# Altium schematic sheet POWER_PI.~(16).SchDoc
size A; SheetNumber: 1; SheetTotal: 2
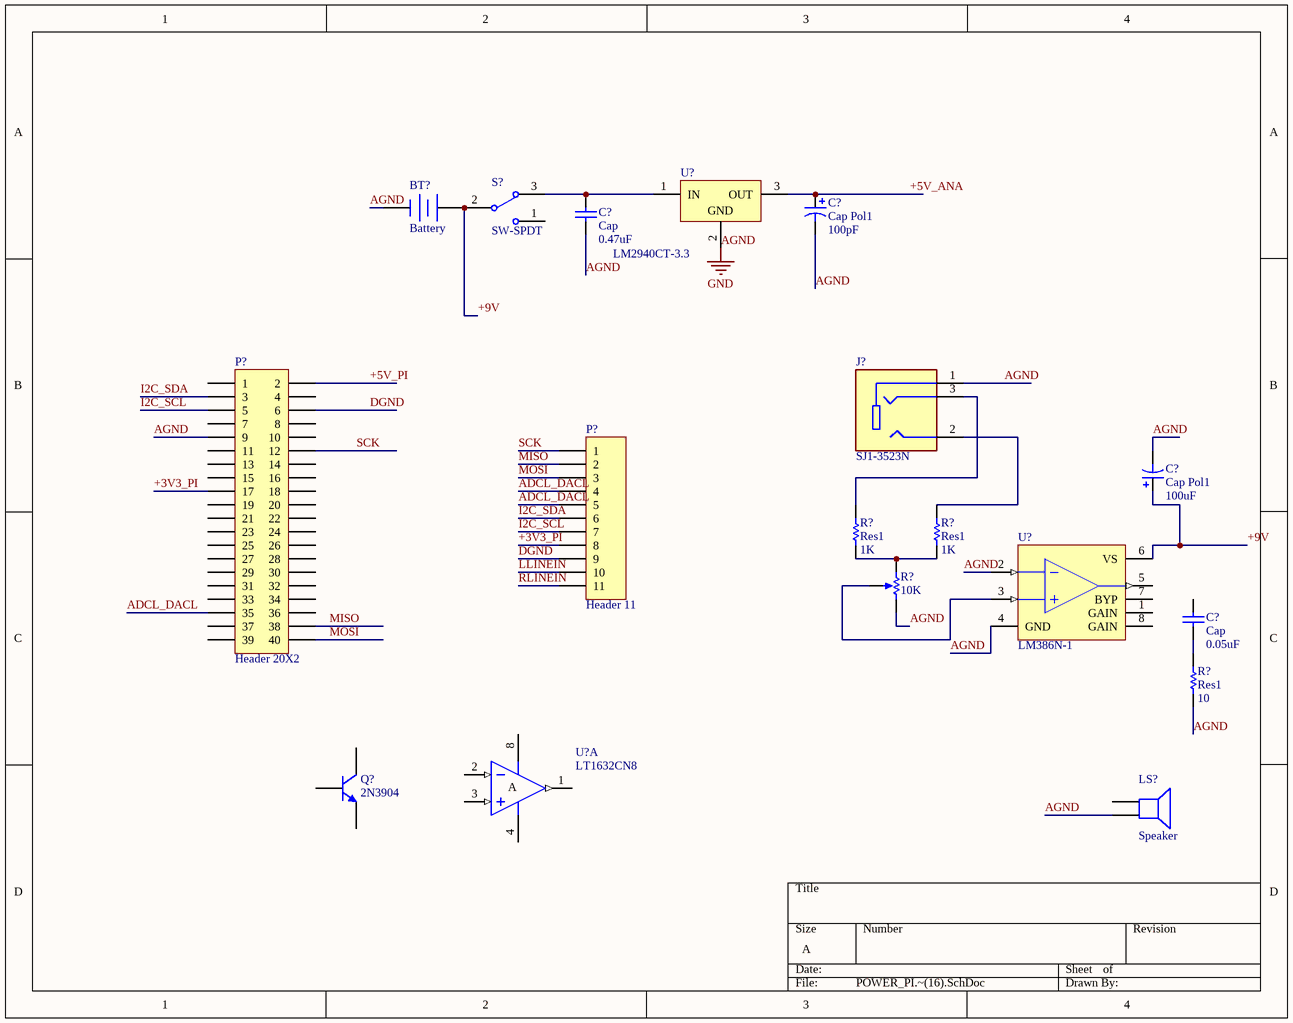
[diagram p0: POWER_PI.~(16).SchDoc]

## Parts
(Parts that share a designator on the sheet are numbered #1, #2 ... from top to bottom, then left to right.)
BT?  Battery  [BAT-2]
C?#1  Cap Pol1  value 100pF  [RB7.6-15]
C?#2  Cap  value 0.47uF  [RAD-0.3]
C?#3  Cap Pol1  value 100uF  [RB7.6-15]
C?#4  Cap  value 0.05uF  [RAD-0.3]
J?  SJ1-3523N  [CUI_SJ1-3523N]
LS?  Speaker  [PIN2]
P?#1  Header 20X2  [HDR2X20]
P?#2  Header 11  [HDR1X11]
Q?  2N3904  [TO92C]
R?#1  Res1  value 1K  [AXIAL-0.3]
R?#2  Res1  value 1K  [AXIAL-0.3]
R?#3  value 10K  [POT OFFSET 200]  (hidden comment: RPot_3)
R?#4  Res1  value 10  [AXIAL-0.3]
S?  SW-SPDT  [SW DPST jameco]
U?#1  LM2940CT-3.3  [T03B]
U?#2  LM386N-1  [DIP-8]
U?#3  LT1632CN8  [SO08]  (part A of 2)

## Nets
AGND: BT?.2(-) C?#1.2 C?#2.1 C?#3.2 J?.1 LS?.2 P?#1.9 R?#3.3(BOT) R?#4.1 U?#1.2(GND) U?#2.2(IN-) U?#2.4(GND)  [also labelled GND]
+3V3_PI: P?#1.17 P?#2.8
+5V_ANA: C?#1.1 U?#1.3(OUT)
+5V_PI: P?#1.2
+9V: BT?.1(+) C?#3.1 S?.2 U?#2.6(VS)
ADCL_DACL: P?#1.35 P?#2.4 P?#2.5
DGND: P?#1.6 P?#2.9
I2C_SCL: P?#1.5 P?#2.7
I2C_SDA: P?#1.3 P?#2.6
LLINEIN: P?#2.10
MISO: P?#1.38 P?#2.2
MOSI: P?#1.40 P?#2.3
RLINEIN: P?#2.11
SCK: P?#1.12 P?#2.1
NetC?#2_2: C?#2.2 S?.3 U?#1.1(IN)
NetC?#4_1: C?#4.1 R?#4.2
NetJ?_2: J?.2 R?#2.2
NetJ?_3: J?.3 R?#1.2
NetR?#1_1: R?#1.1 R?#2.1 R?#3.1(TOP)
NetR?#3_2: R?#3.2(TAP) U?#2.3(IN+)

Not connected (* = marked no-connect by the designer): C?#4 2; LS? 1; P?#1 1 4 7 8 10 11 13 14 15 16 18 19 20 21 22 23 24 25 26 27 28 29 30 31 32 33 34 36 37 39; Q? 1(E) 2(B) 3(C); S? 1; U?#2 1(GAIN) 5(OUT) 7(BYP) 8(GAIN); U?#3 1(OUT) 2(IN-) 3(IN+) 4(V-) 8(V+)

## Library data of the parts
BT? = Battery: Multicell Battery
C?#1 C?#3 = Cap Pol1: Polarized Capacitor (Radial)
C?#2 C?#4 = Cap: Capacitor
J? = SJ1-3523N: 3.5 mm, Stereo, Right Angle, Through Hole, 3 Conductors, 0 Internal Switches, Audio Jack Connector; MF: Same Sky
LS? = Speaker: Loudspeaker
P?#1 = Header 20X2: Header, 20-Pin, Dual row
P?#2 = Header 11: Header, 11-Pin
Q? = 2N3904: NPN General Purpose Amplifier
R?#1 R?#2 R?#4 = Res1: Resistor
R?#3 = RPot: Potentiometer; Sim Note: Enter the Resistance value and the set point into parameter fields.; Set Position: 0.5
S? = SW-SPDT: SPDT Subminiature Toggle Switch, Right Angle Mounting, Vertical Actuation
U?#1 = LM2940CT-5.0: 1A Low Dropout Regulator, 3-pin TO-220; Manufacturer: National Semiconductor; PackageTopMarking: NSUZXYTTE#*LM2940CT*-5.0 P+; PowerWise: N; CompType: LDO IC; High-Reliability: Y
U?#2 = LM386N-1: Low-Voltage Audio Power Amplifier
U?#3 = LT1632CN8: 45MHz, 45V/µs, Dual Rail-to-Rail Input and Output Precision Operational Amplifier; Note: 1455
